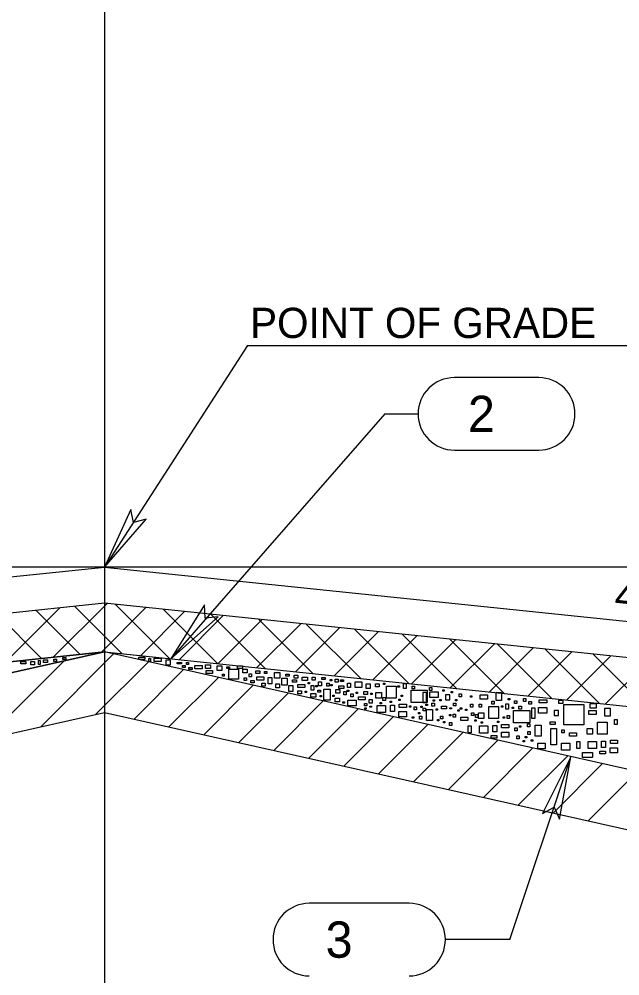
# Model space of a CAD drawing. Extents: x 6561 to 6787, y 19927 to 20919.
# Drawn here: x 6699.64 to 6709.58, y 20861.89 to 20877.71 of the extents above; entities that cross this region are included whole.
import ezdxf

# ---------------------------------------------------------------- set-up
doc = ezdxf.new("R2010")
doc.units = 0
for name, color, linetype in [('Level 1', 7, 'Continuous'), ('Level 10', 7, 'Continuous'), ('Level 3', 7, 'Continuous'), ('Level 4', 7, 'Continuous'), ('Level 8', 7, 'Continuous')]:
    doc.layers.add(name, color=color, linetype=linetype)

msp = doc.modelspace()

# ---------------------------------------------------------------- linework, layer by layer
at = {"layer": 'Level 1'}
for p, q in [((6701.057, 20878.65), (6701.057, 20856.98)), ((6703.419, 20872.316), (6701.057, 20868.65)), ((6703.419, 20872.316), (6709.936, 20872.316)), ((6708.234, 20871.783), (6706.841, 20871.783)), ((6705.69, 20871.183), (6702.152, 20867.132)), ((6705.69, 20871.183), (6706.241, 20871.183)), ((6706.841, 20870.583), (6708.234, 20870.583)), ((6779.047, 20868.65), (6628.473, 20868.65)), ((6707.758, 20862.488), (6708.765, 20865.511)), ((6706.091, 20863.088), (6704.442, 20863.088)), ((6707.758, 20862.488), (6706.691, 20862.488)), ((6706.091, 20861.888), (6706.091, 20861.888))]:
    msp.add_line(p, q, dxfattribs=at)
for points in [[(6701.057, 20868.65), (6701.746, 20869.442), (6701.533, 20869.389), (6701.493, 20869.604)], [(6702.152, 20867.132), (6702.936, 20867.829), (6702.718, 20867.804), (6702.707, 20868.023)], [(6708.765, 20865.511), (6708.295, 20864.573), (6708.488, 20864.677), (6708.579, 20864.478)]]:
    msp.add_lwpolyline(points, close=True, dxfattribs=at)
for centre, start, end in [((6706.841, 20871.183), 90, 270), ((6708.234, 20871.183), 270, 90), ((6704.442, 20862.488), 90, 270), ((6706.091, 20862.488), 270, 90)]:
    msp.add_arc(centre, 0.6, start, end, dxfattribs=at)
at = {"layer": 'Level 10'}
for p, q in [((6701.057, 20867.246), (6690.057, 20864.778)), ((6700.003, 20866.009), (6701.206, 20867.212)), ((6712.057, 20864.778), (6701.057, 20867.246)), ((6699.091, 20865.805), (6700.381, 20867.094)), ((6700.915, 20866.214), (6701.784, 20867.083)), ((6701.544, 20866.136), (6702.361, 20866.953)), ((6702.122, 20866.007), (6702.939, 20866.823)), ((6702.699, 20865.877), (6703.516, 20866.694)), ((6703.277, 20865.747), (6704.094, 20866.564)), ((6703.854, 20865.618), (6704.671, 20866.435)), ((6704.432, 20865.488), (6705.249, 20866.305)), ((6690.057, 20863.778), (6701.057, 20866.246)), ((6701.057, 20866.246), (6712.057, 20863.778)), ((6705.01, 20865.359), (6705.826, 20866.175)), ((6705.587, 20865.229), (6706.404, 20866.046)), ((6706.165, 20865.1), (6706.981, 20865.916)), ((6706.742, 20864.97), (6707.559, 20865.787)), ((6707.32, 20864.84), (6708.136, 20865.657)), ((6707.897, 20864.711), (6708.714, 20865.528)), ((6708.475, 20864.581), (6709.291, 20865.398)), ((6709.052, 20864.452), (6709.869, 20865.268))]:
    msp.add_line(p, q, dxfattribs=at)
at = {"layer": 'Level 3'}
for p, q in [((6701.057, 20868.05), (6687.057, 20866.592)), ((6701.097, 20868.046), (6700.209, 20867.157)), ((6701.349, 20867.215), (6700.565, 20867.999)), ((6715.057, 20866.592), (6701.057, 20868.05)), ((6702.138, 20867.133), (6701.24, 20868.031)), ((6700.013, 20867.137), (6699.284, 20867.865)), ((6700.318, 20867.973), (6699.42, 20867.075)), ((6700.653, 20867.204), (6699.925, 20867.932)), ((6701.738, 20867.979), (6700.998, 20867.239)), ((6702.378, 20867.912), (6701.65, 20867.184)), ((6702.927, 20867.051), (6702.03, 20867.949)), ((6703.019, 20867.846), (6702.29, 20867.117)), ((6703.717, 20866.969), (6702.819, 20867.866)), ((6703.659, 20867.779), (6702.931, 20867.05)), ((6704.299, 20867.712), (6703.571, 20866.984)), ((6704.506, 20866.886), (6703.608, 20867.784)), ((6705.295, 20866.804), (6704.398, 20867.702)), ((6704.94, 20867.645), (6704.211, 20866.917)), ((6705.58, 20867.579), (6704.852, 20866.85)), ((6706.085, 20866.722), (6705.187, 20867.62)), ((6706.874, 20866.64), (6705.976, 20867.537)), ((6706.221, 20867.512), (6705.492, 20866.784)), ((6706.861, 20867.445), (6706.133, 20866.717)), ((6707.663, 20866.557), (6706.766, 20867.455)), ((6707.501, 20867.379), (6706.773, 20866.65)), ((6708.453, 20866.475), (6707.555, 20867.373)), ((6687.057, 20865.787), (6701.057, 20867.246)), ((6701.057, 20867.246), (6715.057, 20865.787)), ((6708.142, 20867.312), (6707.413, 20866.583)), ((6708.782, 20867.245), (6708.054, 20866.517)), ((6709.242, 20866.393), (6708.344, 20867.291)), ((6710.031, 20866.311), (6709.134, 20867.209)), ((6709.423, 20867.178), (6708.694, 20866.45)), ((6710.063, 20867.112), (6709.335, 20866.383))]:
    msp.add_line(p, q, dxfattribs=at)
at = {"layer": 'Level 4'}
for p, q in [((6701.057, 20867.246), (6690.057, 20866.1)), ((6690.057, 20864.778), (6701.057, 20867.246)), ((6701.057, 20867.246), (6712.057, 20866.1)), ((6712.057, 20864.778), (6701.057, 20867.246))]:
    msp.add_line(p, q, dxfattribs=at)
for points in [[(6699.671, 20867.09), (6699.754, 20867.09), (6699.754, 20867.047), (6699.671, 20867.047)], [(6699.896, 20867.034), (6699.837, 20867.034), (6699.837, 20867.085), (6699.896, 20867.085)], [(6699.99, 20867.039), (6699.964, 20867.039), (6699.964, 20867.105), (6699.99, 20867.105)], [(6700.049, 20867.116), (6700.112, 20867.116), (6700.112, 20867.069), (6700.049, 20867.069)], [(6700.216, 20867.125), (6700.261, 20867.125), (6700.261, 20867.088), (6700.216, 20867.088)], [(6700.416, 20867.119), (6700.369, 20867.119), (6700.369, 20867.153), (6700.416, 20867.153)], [(6701.621, 20867.162), (6701.721, 20867.162), (6701.721, 20867.121), (6701.621, 20867.121)], [(6701.816, 20867.088), (6701.79, 20867.088), (6701.79, 20867.139), (6701.816, 20867.139)], [(6701.99, 20867.09), (6701.876, 20867.09), (6701.876, 20867.145), (6701.99, 20867.145)], [(6702.143, 20867.029), (6702.075, 20867.029), (6702.075, 20867.115), (6702.143, 20867.115)], [(6702.255, 20867.072), (6702.33, 20867.072), (6702.33, 20867.047), (6702.255, 20867.047)], [(6702.442, 20867.039), (6702.414, 20867.039), (6702.414, 20867.072), (6702.442, 20867.072)], [(6702.387, 20866.991), (6702.346, 20866.991), (6702.346, 20867.023), (6702.387, 20867.023)], [(6702.507, 20866.958), (6702.452, 20866.958), (6702.452, 20866.988), (6702.507, 20866.988)], [(6702.551, 20867.019), (6702.669, 20867.019), (6702.669, 20866.968), (6702.551, 20866.968)], [(6702.724, 20867.035), (6702.808, 20867.035), (6702.808, 20866.97), (6702.724, 20866.97)], [(6702.843, 20866.89), (6702.739, 20866.89), (6702.739, 20866.941), (6702.843, 20866.941)], [(6702.918, 20867.016), (6702.997, 20867.016), (6702.997, 20866.937), (6702.918, 20866.937)], [(6703.124, 20866.974), (6703.077, 20866.974), (6703.077, 20867.002), (6703.124, 20867.002)], [(6703.273, 20866.795), (6703.114, 20866.795), (6703.114, 20866.961), (6703.273, 20866.961)], [(6703.253, 20867.015), (6703.335, 20867.015), (6703.335, 20866.972), (6703.253, 20866.972)], [(6703.341, 20866.963), (6703.414, 20866.963), (6703.414, 20866.902), (6703.341, 20866.902)], [(6703.624, 20866.888), (6703.559, 20866.888), (6703.559, 20866.933), (6703.624, 20866.933)], [(6703.74, 20866.888), (6703.703, 20866.888), (6703.703, 20866.925), (6703.74, 20866.925)], [(6703.955, 20866.811), (6703.865, 20866.811), (6703.865, 20866.905), (6703.955, 20866.905)], [(6703.036, 20866.843), (6703.006, 20866.843), (6703.006, 20866.876), (6703.036, 20866.876)], [(6703.404, 20866.776), (6703.363, 20866.776), (6703.363, 20866.815), (6703.404, 20866.815)], [(6703.449, 20866.882), (6703.488, 20866.882), (6703.488, 20866.835), (6703.449, 20866.835)], [(6703.473, 20866.772), (6703.528, 20866.772), (6703.528, 20866.737), (6703.473, 20866.737)], [(6703.688, 20866.78), (6703.575, 20866.78), (6703.575, 20866.835), (6703.688, 20866.835)], [(6703.659, 20866.727), (6703.714, 20866.727), (6703.714, 20866.682), (6703.659, 20866.682)], [(6703.822, 20866.721), (6703.763, 20866.721), (6703.763, 20866.823), (6703.822, 20866.823)], [(6704.078, 20866.695), (6703.989, 20866.695), (6703.989, 20866.811), (6704.078, 20866.811)], [(6704.054, 20866.876), (6704.111, 20866.876), (6704.111, 20866.843), (6704.054, 20866.843)], [(6704.232, 20866.745), (6704.165, 20866.745), (6704.165, 20866.783), (6704.232, 20866.783)], [(6704.191, 20866.861), (6704.25, 20866.861), (6704.25, 20866.814), (6704.191, 20866.814)], [(6704.413, 20866.775), (6704.324, 20866.775), (6704.324, 20866.83), (6704.413, 20866.83)], [(6704.447, 20866.721), (6704.423, 20866.721), (6704.423, 20866.743), (6704.447, 20866.743)], [(6704.489, 20866.826), (6704.54, 20866.826), (6704.54, 20866.781), (6704.489, 20866.781)], [(6704.593, 20866.753), (6704.644, 20866.753), (6704.644, 20866.684), (6704.593, 20866.684)], [(6704.703, 20866.788), (6704.648, 20866.788), (6704.648, 20866.824), (6704.703, 20866.824)], [(6704.772, 20866.68), (6704.731, 20866.68), (6704.731, 20866.729), (6704.772, 20866.729)], [(6704.812, 20866.769), (6704.788, 20866.769), (6704.788, 20866.79), (6704.812, 20866.79)], [(6704.867, 20866.796), (6704.918, 20866.796), (6704.918, 20866.747), (6704.867, 20866.747)], [(6705.008, 20866.759), (6704.957, 20866.759), (6704.957, 20866.786), (6705.008, 20866.786)], [(6705.122, 20866.66), (6705.073, 20866.66), (6705.073, 20866.729), (6705.122, 20866.729)], [(6705.199, 20866.751), (6705.309, 20866.751), (6705.309, 20866.657), (6705.199, 20866.657)], [(6705.689, 20866.708), (6705.666, 20866.708), (6705.666, 20866.729), (6705.689, 20866.729)], [(6703.891, 20866.717), (6703.95, 20866.717), (6703.95, 20866.65), (6703.891, 20866.65)], [(6704.105, 20866.693), (6704.171, 20866.693), (6704.171, 20866.591), (6704.105, 20866.591)], [(6704.25, 20866.709), (6704.368, 20866.709), (6704.368, 20866.658), (6704.25, 20866.658)], [(6704.253, 20866.6), (6704.314, 20866.6), (6704.314, 20866.551), (6704.253, 20866.551)], [(6704.396, 20866.576), (6704.372, 20866.576), (6704.372, 20866.598), (6704.396, 20866.598)], [(6704.515, 20866.613), (6704.473, 20866.613), (6704.473, 20866.692), (6704.515, 20866.692)], [(6704.572, 20866.668), (6704.549, 20866.668), (6704.549, 20866.69), (6704.572, 20866.69)], [(6704.581, 20866.612), (6704.625, 20866.612), (6704.625, 20866.58), (6704.581, 20866.58)], [(6704.786, 20866.447), (6704.684, 20866.447), (6704.684, 20866.631), (6704.786, 20866.631)], [(6704.82, 20866.684), (6704.796, 20866.684), (6704.796, 20866.706), (6704.82, 20866.706)], [(6704.879, 20866.625), (6704.949, 20866.625), (6704.949, 20866.562), (6704.879, 20866.562)], [(6704.931, 20866.686), (6705.014, 20866.686), (6705.014, 20866.643), (6704.931, 20866.643)], [(6705.049, 20866.539), (6705.012, 20866.539), (6705.012, 20866.592), (6705.049, 20866.592)], [(6705.093, 20866.594), (6705.069, 20866.594), (6705.069, 20866.615), (6705.093, 20866.615)], [(6705.24, 20866.556), (6705.216, 20866.556), (6705.216, 20866.578), (6705.24, 20866.578)], [(6705.346, 20866.594), (6705.405, 20866.594), (6705.405, 20866.544), (6705.346, 20866.544)], [(6705.45, 20866.643), (6705.383, 20866.643), (6705.383, 20866.721), (6705.45, 20866.721)], [(6705.538, 20866.721), (6705.599, 20866.721), (6705.599, 20866.666), (6705.538, 20866.666)], [(6705.634, 20866.482), (6705.544, 20866.482), (6705.544, 20866.576), (6705.634, 20866.576)], [(6705.716, 20866.682), (6705.877, 20866.682), (6705.877, 20866.482), (6705.716, 20866.482)], [(6705.931, 20866.662), (6705.907, 20866.662), (6705.907, 20866.684), (6705.931, 20866.684)], [(6705.999, 20866.726), (6706.042, 20866.726), (6706.042, 20866.639), (6705.999, 20866.639)], [(6706.392, 20866.411), (6706.125, 20866.411), (6706.125, 20866.612), (6706.392, 20866.612)], [(6706.143, 20866.681), (6706.183, 20866.681), (6706.183, 20866.634), (6706.143, 20866.634)], [(6706.378, 20866.573), (6706.319, 20866.573), (6706.319, 20866.408), (6706.378, 20866.408)], [(6706.428, 20866.657), (6706.467, 20866.657), (6706.467, 20866.61), (6706.428, 20866.61)], [(6706.437, 20866.585), (6706.57, 20866.585), (6706.57, 20866.491), (6706.437, 20866.491)], [(6706.673, 20866.596), (6706.649, 20866.596), (6706.649, 20866.617), (6706.673, 20866.617)], [(6706.81, 20866.57), (6706.787, 20866.57), (6706.787, 20866.592), (6706.81, 20866.592)], [(6707.618, 20866.44), (6707.532, 20866.44), (6707.532, 20866.573), (6707.618, 20866.573)], [(6704.548, 20866.498), (6704.469, 20866.498), (6704.469, 20866.558), (6704.548, 20866.558)], [(6704.643, 20866.501), (6704.619, 20866.501), (6704.619, 20866.523), (6704.643, 20866.523)], [(6704.851, 20866.511), (6704.828, 20866.511), (6704.828, 20866.533), (6704.851, 20866.533)], [(6704.867, 20866.48), (6704.943, 20866.48), (6704.943, 20866.421), (6704.867, 20866.421)], [(6705.022, 20866.401), (6704.998, 20866.401), (6704.998, 20866.423), (6705.022, 20866.423)], [(6705.218, 20866.352), (6705.081, 20866.352), (6705.081, 20866.45), (6705.218, 20866.45)], [(6705.127, 20866.553), (6705.167, 20866.553), (6705.167, 20866.506), (6705.127, 20866.506)], [(6705.367, 20866.451), (6705.253, 20866.451), (6705.253, 20866.506), (6705.367, 20866.506)], [(6705.432, 20866.46), (6705.481, 20866.46), (6705.481, 20866.401), (6705.432, 20866.401)], [(6705.483, 20866.544), (6705.46, 20866.544), (6705.46, 20866.566), (6705.483, 20866.566)], [(6705.659, 20866.492), (6705.699, 20866.492), (6705.699, 20866.445), (6705.659, 20866.445)], [(6705.803, 20866.411), (6705.78, 20866.411), (6705.78, 20866.432), (6705.803, 20866.432)], [(6705.945, 20866.44), (6705.921, 20866.44), (6705.921, 20866.462), (6705.945, 20866.462)], [(6705.984, 20866.507), (6705.96, 20866.507), (6705.96, 20866.529), (6705.984, 20866.529)], [(6706.512, 20866.434), (6706.488, 20866.434), (6706.488, 20866.456), (6706.512, 20866.456)], [(6706.624, 20866.438), (6706.6, 20866.438), (6706.6, 20866.46), (6706.624, 20866.46)], [(6706.692, 20866.451), (6706.766, 20866.451), (6706.766, 20866.538), (6706.692, 20866.538)], [(6706.881, 20866.438), (6706.858, 20866.438), (6706.858, 20866.46), (6706.881, 20866.46)], [(6706.919, 20866.553), (6706.958, 20866.553), (6706.958, 20866.506), (6706.919, 20866.506)], [(6707.13, 20866.497), (6707.107, 20866.497), (6707.107, 20866.519), (6707.13, 20866.519)], [(6707.387, 20866.467), (6707.265, 20866.467), (6707.265, 20866.534), (6707.387, 20866.534)], [(6707.461, 20866.429), (6707.5, 20866.429), (6707.5, 20866.382), (6707.461, 20866.382)], [(6707.755, 20866.456), (6707.731, 20866.456), (6707.731, 20866.478), (6707.755, 20866.478)], [(6707.836, 20866.439), (6707.875, 20866.439), (6707.875, 20866.392), (6707.836, 20866.392)], [(6707.983, 20866.473), (6708.022, 20866.473), (6708.022, 20866.425), (6707.983, 20866.425)], [(6708.073, 20866.427), (6708.113, 20866.427), (6708.113, 20866.38), (6708.073, 20866.38)], [(6708.371, 20866.405), (6708.241, 20866.405), (6708.241, 20866.452), (6708.371, 20866.452)], [(6708.563, 20866.397), (6708.638, 20866.397), (6708.638, 20866.444), (6708.563, 20866.444)], [(6705.395, 20866.354), (6705.352, 20866.354), (6705.352, 20866.393), (6705.395, 20866.393)], [(6705.383, 20866.299), (6705.36, 20866.299), (6705.36, 20866.32), (6705.383, 20866.32)], [(6705.47, 20866.33), (6705.44, 20866.33), (6705.44, 20866.35), (6705.47, 20866.35)], [(6705.563, 20866.36), (6705.701, 20866.36), (6705.701, 20866.242), (6705.563, 20866.242)], [(6705.634, 20866.385), (6705.611, 20866.385), (6705.611, 20866.407), (6705.634, 20866.407)], [(6705.783, 20866.364), (6705.85, 20866.364), (6705.85, 20866.262), (6705.783, 20866.262)], [(6706.046, 20866.172), (6705.924, 20866.172), (6705.924, 20866.258), (6706.046, 20866.258)], [(6705.928, 20866.38), (6706.046, 20866.38), (6706.046, 20866.329), (6705.928, 20866.329)], [(6706.121, 20866.334), (6706.098, 20866.334), (6706.098, 20866.356), (6706.121, 20866.356)], [(6706.177, 20866.337), (6706.216, 20866.337), (6706.216, 20866.29), (6706.177, 20866.29)], [(6706.308, 20866.326), (6706.284, 20866.326), (6706.284, 20866.348), (6706.308, 20866.348)], [(6706.326, 20866.317), (6706.365, 20866.317), (6706.365, 20866.27), (6706.326, 20866.27)], [(6706.394, 20866.362), (6706.371, 20866.362), (6706.371, 20866.383), (6706.394, 20866.383)], [(6706.48, 20866.11), (6706.378, 20866.11), (6706.378, 20866.294), (6706.48, 20866.294)], [(6706.469, 20866.398), (6706.509, 20866.398), (6706.509, 20866.351), (6706.469, 20866.351)], [(6706.563, 20866.285), (6706.54, 20866.285), (6706.54, 20866.307), (6706.563, 20866.307)], [(6706.625, 20866.349), (6706.708, 20866.349), (6706.708, 20866.306), (6706.625, 20866.306)], [(6706.791, 20866.303), (6706.767, 20866.303), (6706.767, 20866.324), (6706.791, 20866.324)], [(6706.825, 20866.4), (6706.864, 20866.4), (6706.864, 20866.353), (6706.825, 20866.353)], [(6706.922, 20866.267), (6706.899, 20866.267), (6706.899, 20866.289), (6706.922, 20866.289)], [(6706.962, 20866.301), (6706.938, 20866.301), (6706.938, 20866.322), (6706.962, 20866.322)], [(6707.046, 20866.275), (6707.022, 20866.275), (6707.022, 20866.297), (6707.046, 20866.297)], [(6707.107, 20866.38), (6707.147, 20866.38), (6707.147, 20866.333), (6707.107, 20866.333)], [(6707.251, 20866.38), (6707.29, 20866.38), (6707.29, 20866.333), (6707.251, 20866.333)], [(6707.41, 20866.345), (6707.571, 20866.345), (6707.571, 20866.145), (6707.41, 20866.145)], [(6707.643, 20866.334), (6707.619, 20866.334), (6707.619, 20866.356), (6707.643, 20866.356)], [(6707.693, 20866.389), (6707.736, 20866.389), (6707.736, 20866.302), (6707.693, 20866.302)], [(6707.818, 20866.313), (6707.794, 20866.313), (6707.794, 20866.334), (6707.818, 20866.334)], [(6708.086, 20866.074), (6707.819, 20866.074), (6707.819, 20866.275), (6708.086, 20866.275)], [(6707.908, 20866.349), (6707.948, 20866.349), (6707.948, 20866.302), (6707.908, 20866.302)], [(6708.175, 20866.315), (6708.116, 20866.315), (6708.116, 20866.15), (6708.175, 20866.15)], [(6708.233, 20866.326), (6708.367, 20866.326), (6708.367, 20866.232), (6708.233, 20866.232)], [(6708.489, 20866.193), (6708.563, 20866.193), (6708.563, 20866.279), (6708.489, 20866.279)], [(6708.65, 20866.374), (6708.983, 20866.374), (6708.983, 20866.04), (6708.65, 20866.04)], [(6709.184, 20866.209), (6709.062, 20866.209), (6709.062, 20866.275), (6709.184, 20866.275)], [(6709.191, 20866.389), (6709.082, 20866.389), (6709.082, 20866.319), (6709.191, 20866.319)], [(6709.415, 20866.181), (6709.329, 20866.181), (6709.329, 20866.315), (6709.415, 20866.315)], [(6706.168, 20866.151), (6706.145, 20866.151), (6706.145, 20866.173), (6706.168, 20866.173)], [(6706.269, 20866.224), (6706.245, 20866.224), (6706.245, 20866.246), (6706.269, 20866.246)], [(6706.265, 20866.182), (6706.304, 20866.182), (6706.304, 20866.135), (6706.265, 20866.135)], [(6706.585, 20866.106), (6706.561, 20866.106), (6706.561, 20866.128), (6706.585, 20866.128)], [(6706.609, 20866.184), (6706.648, 20866.184), (6706.648, 20866.137), (6706.609, 20866.137)], [(6706.685, 20866.073), (6706.661, 20866.073), (6706.661, 20866.094), (6706.685, 20866.094)], [(6706.783, 20866.191), (6706.759, 20866.191), (6706.759, 20866.212), (6706.783, 20866.212)], [(6706.821, 20866.216), (6706.861, 20866.216), (6706.861, 20866.168), (6706.821, 20866.168)], [(6707.061, 20866.113), (6706.947, 20866.113), (6706.947, 20866.168), (6707.061, 20866.168)], [(6707.123, 20866.241), (6707.162, 20866.241), (6707.162, 20866.194), (6707.123, 20866.194)], [(6707.201, 20866.102), (6707.178, 20866.102), (6707.178, 20866.124), (6707.201, 20866.124)], [(6707.188, 20866.211), (6707.227, 20866.211), (6707.227, 20866.164), (6707.188, 20866.164)], [(6707.328, 20866.145), (6707.238, 20866.145), (6707.238, 20866.239), (6707.328, 20866.239)], [(6707.574, 20866.081), (6707.551, 20866.081), (6707.551, 20866.102), (6707.574, 20866.102)], [(6707.67, 20866.151), (6707.647, 20866.151), (6707.647, 20866.173), (6707.67, 20866.173)], [(6707.712, 20866.194), (6707.751, 20866.194), (6707.751, 20866.146), (6707.712, 20866.146)], [(6709.49, 20866.13), (6709.533, 20866.13), (6709.533, 20866.043), (6709.49, 20866.043)], [(6706.76, 20866.078), (6706.799, 20866.078), (6706.799, 20866.03), (6706.76, 20866.03)], [(6707.116, 20865.909), (6707.069, 20865.909), (6707.069, 20866.023), (6707.116, 20866.023)], [(6707.257, 20866.023), (6707.395, 20866.023), (6707.395, 20865.905), (6707.257, 20865.905)], [(6707.305, 20866.069), (6707.282, 20866.069), (6707.282, 20866.091), (6707.305, 20866.091)], [(6707.477, 20866.027), (6707.544, 20866.027), (6707.544, 20865.925), (6707.477, 20865.925)], [(6707.622, 20866.043), (6707.74, 20866.043), (6707.74, 20865.992), (6707.622, 20865.992)], [(6707.842, 20865.989), (6707.881, 20865.989), (6707.881, 20865.942), (6707.842, 20865.942)], [(6707.939, 20866.004), (6707.916, 20866.004), (6707.916, 20866.026), (6707.939, 20866.026)], [(6708.048, 20866.056), (6708.087, 20866.056), (6708.087, 20866.009), (6708.048, 20866.009)], [(6708.277, 20865.851), (6708.175, 20865.851), (6708.175, 20866.036), (6708.277, 20866.036)], [(6708.422, 20866.091), (6708.504, 20866.091), (6708.504, 20866.047), (6708.422, 20866.047)], [(6708.434, 20865.981), (6708.528, 20865.981), (6708.528, 20865.709), (6708.434, 20865.709)], [(6708.618, 20865.957), (6708.658, 20865.957), (6708.658, 20865.91), (6708.618, 20865.91)], [(6709.125, 20865.886), (6709.034, 20865.886), (6709.034, 20865.981), (6709.125, 20865.981)], [(6709.207, 20866.087), (6709.368, 20866.087), (6709.368, 20865.886), (6709.207, 20865.886)], [(6707.544, 20865.819), (6707.45, 20865.819), (6707.45, 20865.862), (6707.544, 20865.862)], [(6707.74, 20865.834), (6707.618, 20865.834), (6707.618, 20865.921), (6707.74, 20865.921)], [(6707.873, 20865.856), (6707.912, 20865.856), (6707.912, 20865.808), (6707.873, 20865.808)], [(6708.002, 20865.76), (6707.979, 20865.76), (6707.979, 20865.782), (6708.002, 20865.782)], [(6708.036, 20865.827), (6708.012, 20865.827), (6708.012, 20865.849), (6708.036, 20865.849)], [(6708.054, 20865.928), (6708.093, 20865.928), (6708.093, 20865.881), (6708.054, 20865.881)], [(6708.136, 20865.77), (6708.112, 20865.77), (6708.112, 20865.792), (6708.136, 20865.792)], [(6708.858, 20865.855), (6708.744, 20865.855), (6708.744, 20865.91), (6708.858, 20865.91)], [(6709.419, 20865.784), (6709.537, 20865.784), (6709.537, 20865.733), (6709.419, 20865.733)], [(6708.339, 20865.643), (6708.222, 20865.643), (6708.222, 20865.737), (6708.339, 20865.737)], [(6708.61, 20865.737), (6708.748, 20865.737), (6708.748, 20865.619), (6708.61, 20865.619)], [(6708.913, 20865.65), (6708.866, 20865.65), (6708.866, 20865.764), (6708.913, 20865.764)], [(6709.054, 20865.764), (6709.191, 20865.764), (6709.191, 20865.647), (6709.054, 20865.647)], [(6709.274, 20865.768), (6709.341, 20865.768), (6709.341, 20865.666), (6709.274, 20865.666)], [(6709.537, 20865.576), (6709.415, 20865.576), (6709.415, 20865.662), (6709.537, 20865.662)], [(6709.125, 20865.501), (6708.956, 20865.501), (6708.956, 20865.58), (6709.125, 20865.58)], [(6709.341, 20865.56), (6709.246, 20865.56), (6709.246, 20865.603), (6709.341, 20865.603)]]:
    msp.add_lwpolyline(points, close=True, dxfattribs=at)
at = {"layer": 'Level 8'}
for p, q in [((6687.057, 20867.192), (6701.057, 20868.65)), ((6701.057, 20868.65), (6715.057, 20867.192)), ((6701.057, 20868.05), (6687.057, 20866.592)), ((6715.057, 20866.592), (6701.057, 20868.05))]:
    msp.add_line(p, q, dxfattribs=at)

# ---------------------------------------------------------------- texts
at = {"layer": 'Level 1'}
for s, height, p in [('POINT OF GRADE', 0.5, (6703.463, 20872.438)), (' 2', 0.6, (6706.841, 20870.883)), (' 3', 0.6, (6704.488, 20862.188))]:
    msp.add_text(s, height=height, dxfattribs=at).set_placement(p)
msp.add_text('48:1', height=0.5, rotation=354.0531, dxfattribs=at).set_placement((6709.474, 20867.949))

doc.saveas('drawing.dxf')
